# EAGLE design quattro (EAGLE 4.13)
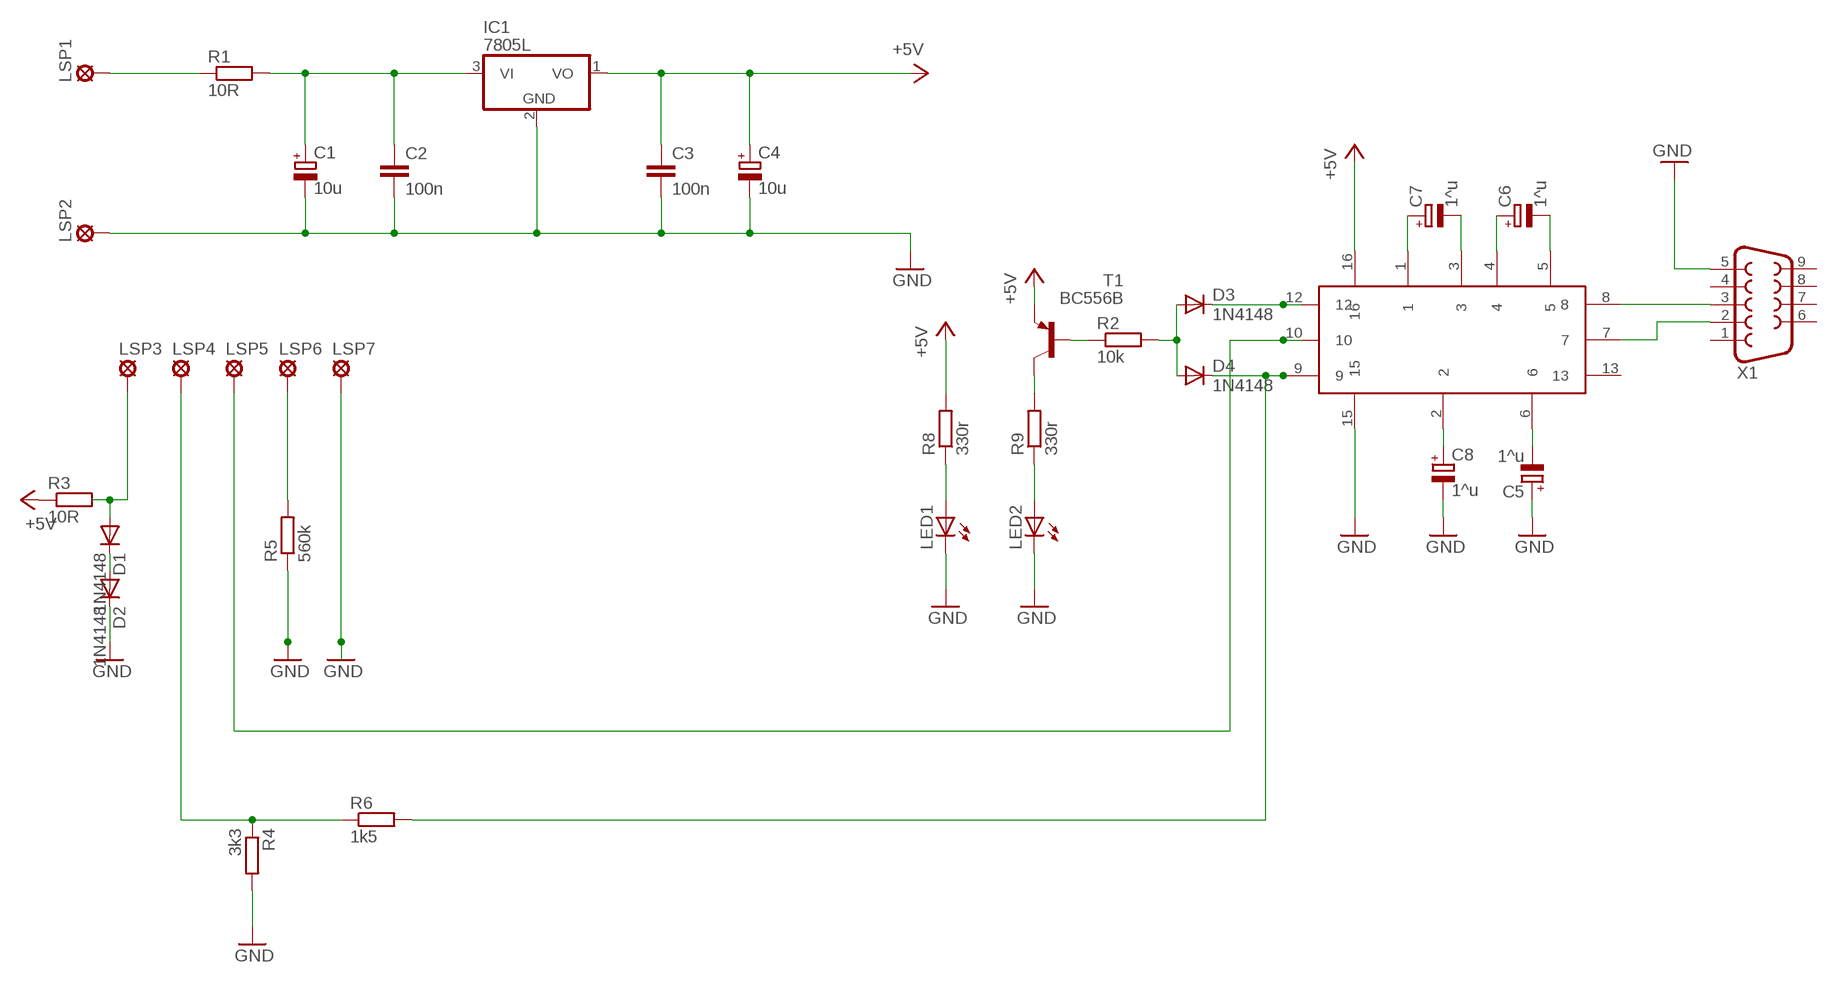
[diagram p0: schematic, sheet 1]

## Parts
C1  10u  CPOL-EUE5-5  [E5-5]
C2  100n  C-EU050-024X044  [C050-024X044]
C3  100n  C-EU050-024X044  [C050-024X044]
C4  10u  CPOL-EUE5-5  [E5-5]
C5  1^u  CPOL-EUE5-5  [E5-5]
C6  1^u  CPOL-EUE5-5  [E5-5]
C7  1^u  CPOL-EUE5-5  [E5-5]
C8  1^u  CPOL-EUE5-5  [E5-5]
D1  1N4148  [DO35-10]
D2  1N4148  [DO35-10]
D3  1N4148  [DO35-10]
D4  1N4148  [DO35-10]
IC1  7805L  [TO92]
IC2  MAX232SPEZIAL  [DIL16]
LED1  LED3MM  [LED3MM]
LED2  LED3MM  [LED3MM]
LSP1  12V  LSP10  [LSP10]
LSP2  GND  LSP10  [LSP10]
LSP3  LSP10  [LSP10]
LSP4  LSP10  [LSP10]
LSP5  LSP10  [LSP10]
LSP6  LSP10  [LSP10]
LSP7  LSP10  [LSP10]
R1  10R  R-EU_0207/15  [0207/15]
R2  10k  R-EU_0207/15  [0207/15]
R3  10R  R-EU_0207/15  [0207/15]
R4  3k3  R-EU_0207/15  [0207/15]
R5  560k  R-EU_0207/15  [0207/15]
R6  1k5  R-EU_0207/15  [0207/15]
R8  330r  R-EU_0207/15  [0207/15]
R9  330r  R-EU_0207/15  [0207/15]
T1  BC556B  BC556  [TO92-EBC]
X1  F09H  [F09H]

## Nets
+5V: C3.1 C4.+ IC1.1(VO) IC2.16 R3.1 R8.2 T1.E
GND [user1]: C1.- C2.2 C3.2 C4.- C5.+ C8.- D2.C IC1.2(GND) IC2.15 LED1.K(C) LED2.K(C) LSP2.MP LSP7.MP R4.2 R5.1 X1.5
N$1: LSP1.MP R1.1
N$2: C1.+ C2.1 IC1.3(VI) R1.2
N$3: D1.A LSP3.MP R3.2
N$4: D1.C D2.A
N$5: LSP6.MP R5.2
N$6: R2.1 T1.B
N$7: LED2.A R9.1
N$8: LED1.A R8.1
N$9: R9.2 T1.C
N$10: IC2.10 LSP5.MP
N$11: D3.C IC2.12
N$13: C7.+ IC2.1
N$15: D3.A D4.A R2.2
N$16: C7.- IC2.3
N$18: C6.+ IC2.4
N$19: C6.- IC2.5
N$20: C8.+ IC2.2
N$21: C5.- IC2.6
N$22: LSP4.MP R4.1 R6.1
N$23: D4.C IC2.9 R6.2
N$24: IC2.7 X1.2
N$25: IC2.8 X1.3
Unconnected: IC2.13 X1.1 X1.4 X1.6 X1.7 X1.8 X1.9

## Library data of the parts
C1 C4-C8 = rcl:CPOL-EU: POLARIZED CAPACITOR, European symbol
C2 C3 = rcl:C-EU: CAPACITOR, European symbol
D1-D4 = diode:1N4148: DIODE
IC1 = linear:78*: Positive VOLTAGE REGULATOR
IC2 = maxim:MAX232SPEZIAL
LED1 LED2 = led:LED: LED
LSP1-LSP7 = solpad:LSP10: SOLDER PAD
R1-R6 R8 R9 = rcl:R-EU_: RESISTOR, European symbol
T1 = transistor-pnp:BC556*: PNP Transistror
X1 = con-subd:F09: SUB-D

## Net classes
0 default: width 0.508 mm, drill 0.508 mm, clearance 0.508 mm
1 user1: width 0.508 mm, drill 0.508 mm, clearance 0.508 mm

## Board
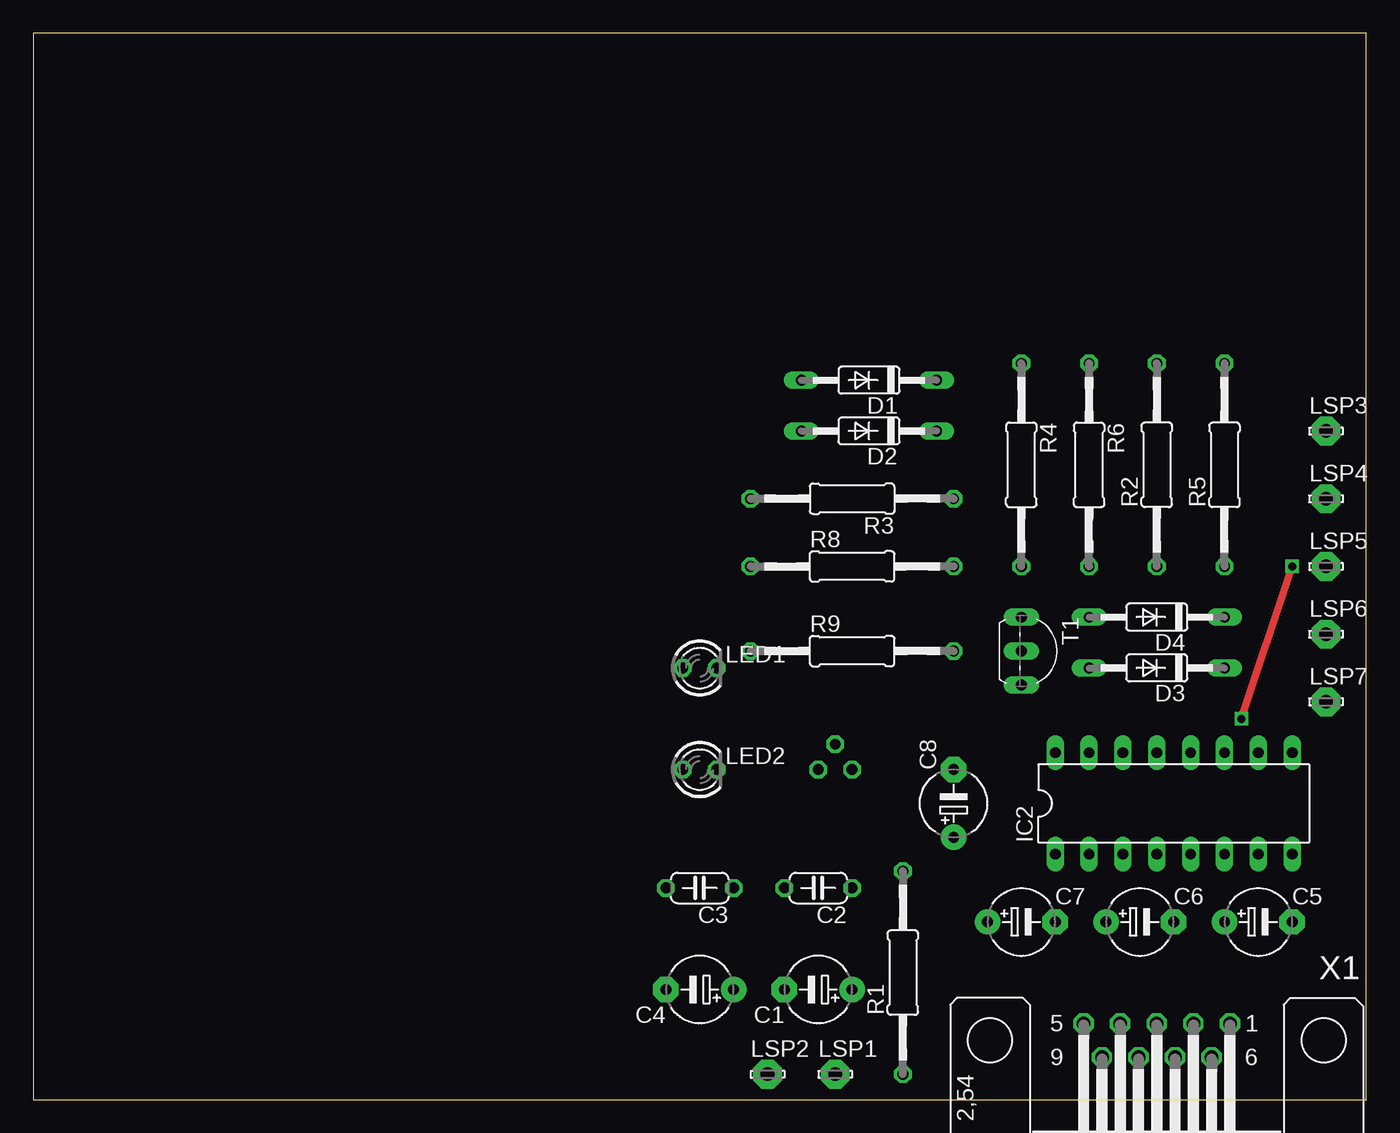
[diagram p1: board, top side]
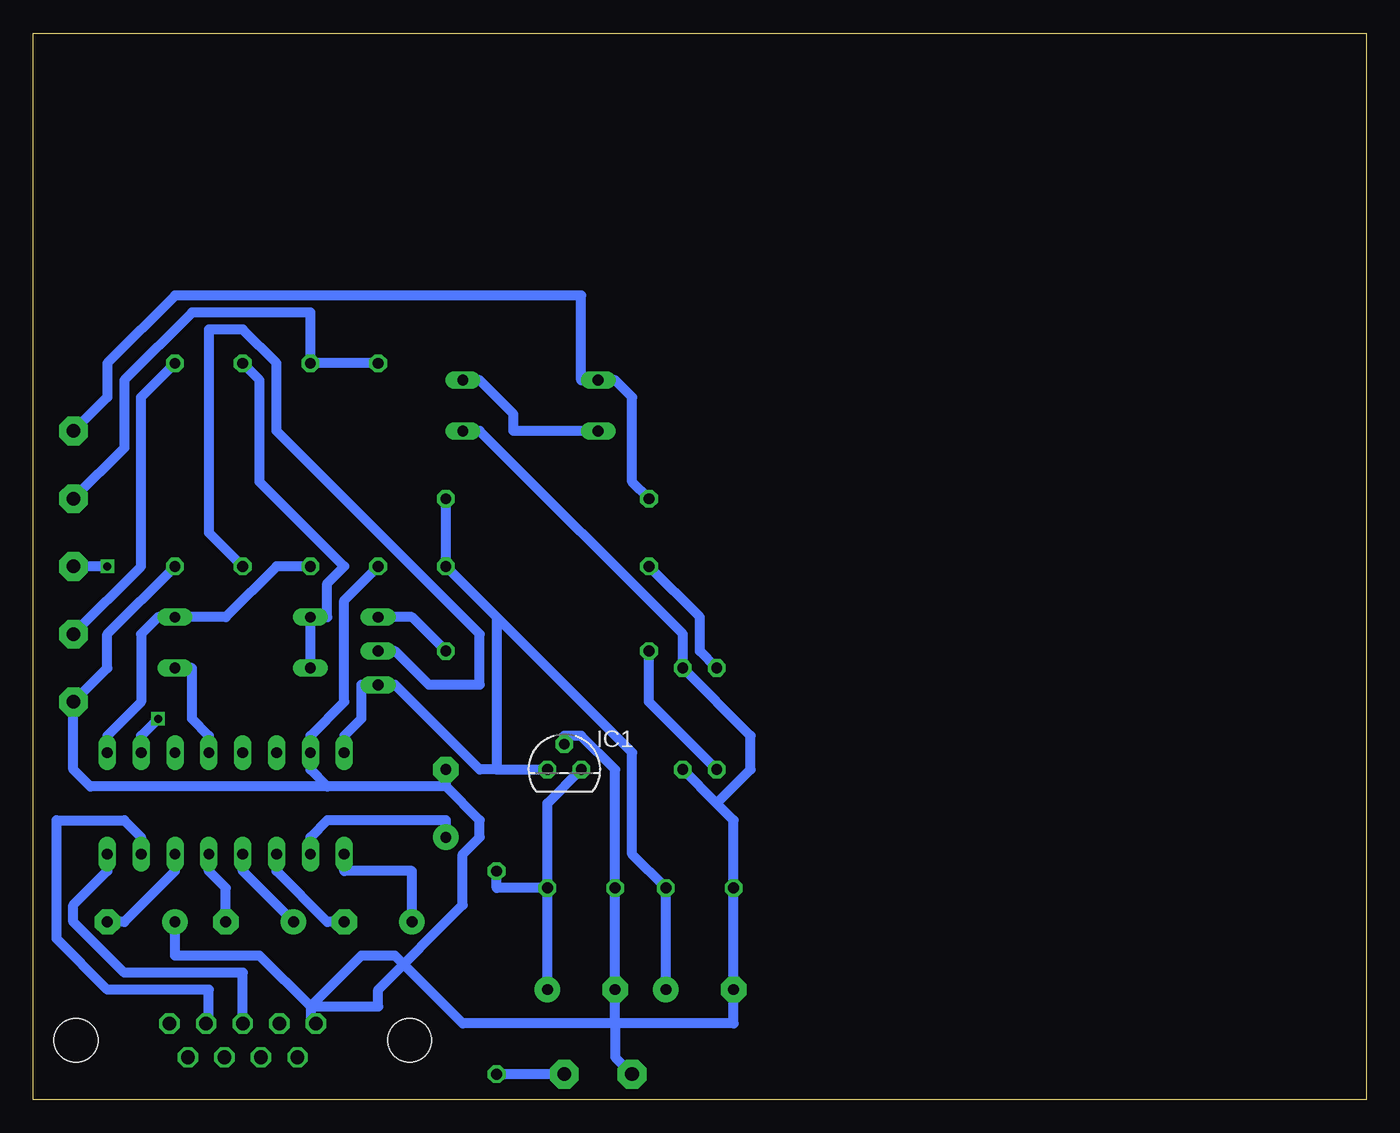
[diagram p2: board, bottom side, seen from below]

Size 100 x 80 mm. Coordinates in mm from the lower left corner, seen from the top.
Outline: 0,0 100,0 100,80 0,80 0,0
Copper layers (1*16): Top 0.035mm / dielectric 1.5mm / Bottom 0.035mm
Design rules "default": minimum track width 10mil, minimum drill 24mil, track to track 8mil, track to pad 8mil, pad to pad 8mil, via to via 8mil, smd to smd 8mil, copper to edge 40mil, drill to drill 8mil, minimum pad ring 10mil, minimum via ring 8mil, stop-mask expansion 4mil, vias tented up to drill 0mil, thermal gap 10mil

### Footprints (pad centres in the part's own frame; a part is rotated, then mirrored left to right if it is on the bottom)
E5-5 = drill 0.813 pad 1.905 round: + -2.54,0 | drill 0.813 pad 1.905 octagon: - 2.54,0
C050-024X044 = drill 0.813 octagon: 1 -2.54,0; 2 2.54,0
DO35-10 = drill 0.813 long: A 5.08,0; C -5.08,0
TO92 = drill 0.813 octagon: 1 -1.27,0; 2 0,1.905; 3 1.27,0
DIL16 = drill 0.813 long: 1 -8.89,-3.81; 2 -6.35,-3.81; 3 -3.81,-3.81; 4 -1.27,-3.81; 5 1.27,-3.81; 6 3.81,-3.81; 7 6.35,-3.81; 8 8.89,-3.81; 9 8.89,3.81; 10 6.35,3.81; 11 3.81,3.81; 12 1.27,3.81; 13 -1.27,3.81; 14 -3.81,3.81; 15 -6.35,3.81; 16 -8.89,3.81
LED3MM = drill 0.813 octagon: A -1.27,0; K 1.27,0
LSP10 = drill 1.016 pad 2.159 octagon: MP 0,0
0207/15 = drill 0.813 octagon: 1 -7.62,0; 2 7.62,0
TO92-EBC = drill 0.813 long: B 0,-1.27; C -2.54,-1.27; E 2.54,-1.27
F09H = drill 1.016 octagon: 1 -5.486,-1.27; 2 -2.743,-1.27; 3 0,-1.27; 4 2.743,-1.27; 5 5.486,-1.27; 6 -4.115,1.27; 7 -1.372,1.27; 8 1.372,1.27; 9 4.115,1.27 | hole 3.302: -12.522,0; 12.522,0

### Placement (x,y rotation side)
C1  58.89,8.25 180 top
C2  58.89,15.87 180 top
C3  50,15.87 180 top
C4  50,8.25 180 top
C5  91.91,13.33 0 top
C6  83.02,13.33 0 top
C7  74.13,13.33 0 top
C8  69.05,22.22 90 top
D1  62.7,53.97 180 top
D2  62.7,50.16 180 top
D3  84.29,32.38 180 top
D4  84.29,36.19 180 top
IC1  60.16,24.76 0 bottom
IC2  85.56,22.22 0 top
LED1  50,32.38 0 top
LED2  50,24.76 0 top
LSP1  60.16,1.9 0 top
LSP2  55.08,1.9 0 top
LSP3  96.99,50.16 0 top
LSP4  96.99,45.08 0 top
LSP5  96.99,40 0 top
LSP6  96.99,34.92 0 top
LSP7  96.99,29.84 0 top
R1  65.24,9.52 90 top
R2  84.29,47.62 90 top
R3  61.43,45.08 180 top
R4  74.13,47.62 270 top
R5  89.37,47.62 90 top
R6  79.21,47.62 270 top
R8  61.43,40 0 top
R9  61.43,33.65 0 top
T1  75.4,33.65 270 top
X1  84.29,4.44 180 top

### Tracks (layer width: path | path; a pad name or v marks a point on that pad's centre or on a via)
+5V
  Bottom 0.737: C4.+ C3.1 55.08,18.41 55.08,26.03 65.24,36.19 | R3.1 R8.2 65.24,36.19 | 65.24,24.76 66.51,24.76 72.86,31.11 T1.E 75.4,31.11 75.4,28.57 76.67,27.3 IC2.16 | 65.24,24.76 IC1.1 | 65.24,36.19 65.24,24.76
GND
  Bottom 0.737: 79.21,6.98 79.21,5.71 X1.5 | 79.21,6.98 83.02,10.79 89.37,10.79 C5.+ | R5.1 94.45,34.92 94.45,32.38 LSP7.MP 96.99,24.76 95.72,23.49 77.94,23.49 | 77.94,23.49 79.21,24.76 IC2.15 79.21,27.3 76.67,29.84 76.67,37.46 R4.2 | 69.05,23.49 77.94,23.49 | 69.05,23.49 C8.- | 79.21,6.98 74.13,6.98 74.13,8.25 67.78,14.6 67.78,18.41 66.51,19.68 66.51,20.95 69.05,23.49 | IC1.2 60.16,27.3 58.89,27.3 56.35,24.76 C2.2 C1.- 56.35,5.71 | LSP2.MP 56.35,3.17 56.35,5.71 | 48.73,22.22 47.46,20.95 C3.2 C4.- 47.46,5.71 56.35,5.71 | 48.73,22.22 LED2.K | 48.73,22.22 46.19,24.76 46.19,27.3 LED1.K 51.27,34.92 66.51,50.16 D2.C | 79.21,6.98 75.4,10.79 72.86,10.79 67.78,5.71 56.35,5.71
N$1
  Bottom 0.737: LSP1.MP R1.1
N$2
  Bottom 0.737: C2.1 65.24,15.87 R1.2 | IC1.3 61.43,22.22 C2.1 | C1.+ C2.1
N$3
  Bottom 0.737: R3.2 55.08,46.35 55.08,52.7 56.35,53.97 D1.A 58.89,53.97 58.89,60.32 89.37,60.32 94.45,55.24 94.45,52.7 LSP3.MP
N$4
  Bottom 0.737: D2.A 63.97,50.16 63.97,51.43 66.51,53.97 D1.C
N$5
  Bottom 0.737: R5.2 91.91,52.7 91.91,40 LSP6.MP
N$6
  Bottom 0.737: R2.1 86.83,42.54 86.83,57.78 84.29,57.78 81.75,55.24 81.75,50.16 66.51,34.92 66.51,31.11 70.32,31.11 72.86,33.65 T1.B
N$7
  Bottom 0.737: LED2.A 53.81,29.84 R9.1
N$8
  Bottom 0.737: LED1.A 50,33.65 50,36.19 R8.1
N$9
  Bottom 0.737: R9.2 71.59,36.19 T1.C
N$10  (via drill 0.6)
  Top 0.508: v90.64,28.57 v94.45,40
  Bottom 0.737: IC2.10 91.91,27.3 v90.64,28.57 | v94.45,40 LSP5.MP
N$11
  Bottom 0.737: IC2.12 86.83,27.3 88.1,28.57 88.1,32.38 D3.C
N$13
  Bottom 0.737: C7.+ 71.59,17.14 76.67,17.14 IC2.1
N$15
  Bottom 0.737: D3.A D4.A 77.94,36.19 77.94,38.73 76.67,40 83.02,46.35 83.02,53.97 R2.2
N$16
  Bottom 0.737: C7.- 77.94,13.33 81.75,17.14 IC2.3
N$18
  Bottom 0.737: C6.+ 84.29,17.14 IC2.4
N$19
  Bottom 0.737: C6.- 85.56,15.87 86.83,17.14 IC2.5
N$20
  Bottom 0.737: C8.+ 69.05,20.95 77.94,20.95 79.21,19.68 IC2.2
N$21
  Bottom 0.737: C5.- 93.18,13.33 89.37,17.14 IC2.6
N$22
  Bottom 0.737: R4.1 R6.1 79.21,59.05 88.1,59.05 93.18,53.97 93.18,48.89 LSP4.MP
N$23
  Bottom 0.737: IC2.9 94.45,27.3 91.91,29.84 91.91,34.92 90.64,36.19 D4.C 85.56,36.19 81.75,40 R6.2
N$24
  Bottom 0.737: IC2.7 91.91,19.68 93.18,20.95 98.26,20.95 98.26,12.06 94.45,8.25 86.83,8.25 86.83,5.71 X1.2
N$25
  Bottom 0.737: X1.3 84.29,9.52 93.18,9.52 96.99,13.33 96.99,14.6 94.45,17.14 IC2.8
